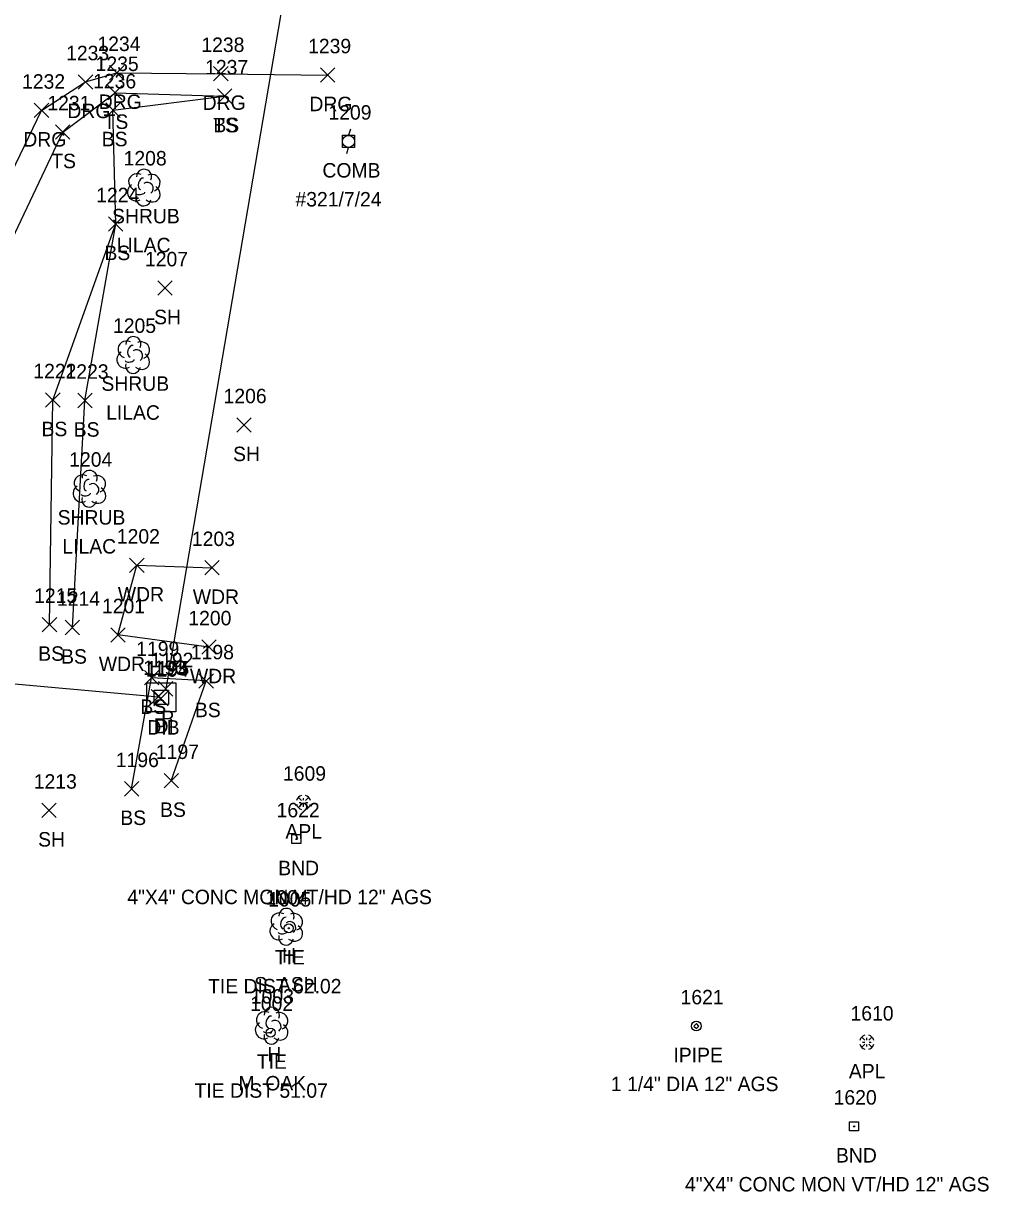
# Model space of a CAD drawing. Extents: x 1618262 to 1622220, y 273782 to 283685.
# Drawn here: x 1622086.2 to 1622219.5, y 282421 to 282582.4 of the extents above; entities that cross this region are included whole.
import ezdxf

# ---------------------------------------------------------------- set-up
doc = ezdxf.new("R2010")
doc.units = 0
for name, color, linetype in [('C_A', 7, 'Continuous'), ('C_C', 7, 'Continuous'), ('C_I', 7, 'Continuous'), ('CBP', 7, 'Continuous'), ('D_A', 7, 'Continuous'), ('D_I', 7, 'Continuous'), ('D_TIC', 7, 'Continuous'), ('DCP', 7, 'Continuous'), ('DS', 7, 'Continuous'), ('L_A', 7, 'Continuous'), ('L_C', 7, 'Continuous'), ('L_I', 7, 'Continuous'), ('L_TIC', 7, 'Continuous'), ('LAWA', 7, 'Continuous'), ('LELB', 7, 'Continuous'), ('LSH', 7, 'Continuous'), ('LTD', 7, 'Continuous'), ('M_A', 7, 'Continuous'), ('M_C', 7, 'Continuous'), ('M_I', 7, 'Continuous'), ('MHBP', 7, 'Continuous'), ('MMP', 7, 'Continuous'), ('MPIP', 7, 'Continuous'), ('R_A', 7, 'Continuous'), ('R_I', 7, 'Continuous'), ('R_TIC', 7, 'Continuous'), ('RDG', 7, 'Continuous'), ('U_A', 7, 'Continuous'), ('U_C', 7, 'Continuous'), ('U_I', 7, 'Continuous'), ('UP', 7, 'Continuous')]:
    doc.layers.add(name, color=color, linetype=linetype)

msp = doc.modelspace()

# ---------------------------------------------------------------- linework, layer by layer
at = {"layer": 'CBP'}
for centre, radius in [((1622122.83, 282457.39), 0.625), ((1622122.83, 282457.39), 0.0833), ((1622120.33, 282442.97), 0.625), ((1622120.33, 282442.97), 0.0833)]:
    msp.add_circle(centre, radius, dxfattribs=at)
at = {"layer": 'D_TIC'}
for points in [[(1622104.82, 282489.47), (1622106.82, 282491.47)], [(1622106.82, 282489.47), (1622104.82, 282491.47)], [(1622103.81, 282488.39), (1622105.81, 282490.39)], [(1622105.81, 282488.39), (1622103.81, 282490.39)], [(1622104.18, 282488.15), (1622106.18, 282490.15)], [(1622106.18, 282488.15), (1622104.18, 282490.15)]]:
    msp.add_lwpolyline(points, dxfattribs=at)
at = {"layer": 'DCP'}
for points in [[(1622123.83, 282596.22), (1622105.82, 282490.47)], [(1622012.08, 282497.76), (1622104.81, 282489.39)]]:
    msp.add_lwpolyline(points, dxfattribs=at)
at = {"layer": 'DS'}
for p, q in [((1622103.22, 282491.31), (1622107.22, 282491.31)), ((1622103.22, 282487.31), (1622103.22, 282491.31)), ((1622107.22, 282491.31), (1622107.22, 282487.31)), ((1622104.22, 282488.31), (1622104.22, 282490.31)), ((1622104.22, 282490.31), (1622106.22, 282490.31)), ((1622105.23, 282489.31), (1622105.23, 282489.31)), ((1622105.23, 282489.31), (1622105.23, 282489.31)), ((1622106.22, 282490.31), (1622106.22, 282488.31)), ((1622106.22, 282488.31), (1622104.22, 282488.31)), ((1622107.22, 282487.31), (1622103.22, 282487.31))]:
    msp.add_line(p, q, dxfattribs=at)
at = {"layer": 'L_TIC'}
for points in [[(1622097.83, 282571.85), (1622099.83, 282573.85)], [(1622099.83, 282571.85), (1622097.83, 282573.85)], [(1622112.97, 282571.38), (1622114.97, 282573.38)], [(1622114.97, 282571.38), (1622112.97, 282573.38)], [(1622112.97, 282571.38), (1622114.97, 282573.38)], [(1622114.97, 282571.38), (1622112.97, 282573.38)], [(1622097.53, 282569.45), (1622099.53, 282571.45)], [(1622099.53, 282569.45), (1622097.53, 282571.45)], [(1622090.59, 282566.42), (1622092.59, 282568.42)], [(1622092.59, 282566.42), (1622090.59, 282568.42)], [(1622097.92, 282553.72), (1622099.92, 282555.72)], [(1622099.92, 282553.72), (1622097.92, 282555.72)], [(1622097.92, 282553.72), (1622099.92, 282555.72)], [(1622099.92, 282553.72), (1622097.92, 282555.72)], [(1622104.73, 282544.86), (1622106.73, 282546.86)], [(1622106.73, 282544.86), (1622104.73, 282546.86)], [(1622089.22, 282529.39), (1622091.22, 282531.39)], [(1622091.22, 282529.39), (1622089.22, 282531.39)], [(1622093.67, 282529.32), (1622095.67, 282531.32)], [(1622095.67, 282529.32), (1622093.67, 282531.32)], [(1622115.64, 282525.94), (1622117.64, 282527.94)], [(1622117.64, 282525.94), (1622115.64, 282527.94)], [(1622100.84, 282506.55), (1622102.84, 282508.55)], [(1622102.84, 282506.55), (1622100.84, 282508.55)], [(1622111.21, 282506.21), (1622113.21, 282508.21)], [(1622113.21, 282506.21), (1622111.21, 282508.21)], [(1622088.76, 282498.35), (1622090.76, 282500.35)], [(1622090.76, 282498.35), (1622088.76, 282500.35)], [(1622091.93, 282497.95), (1622093.93, 282499.95)], [(1622093.93, 282497.95), (1622091.93, 282499.95)], [(1622098.22, 282496.92), (1622100.22, 282498.92)], [(1622100.22, 282496.92), (1622098.22, 282498.92)], [(1622110.8, 282495.25), (1622112.8, 282497.25)], [(1622112.8, 282495.25), (1622110.8, 282497.25)], [(1622102.88, 282491.01), (1622104.88, 282493.01)], [(1622104.88, 282491.01), (1622102.88, 282493.01)], [(1622102.88, 282491.01), (1622104.88, 282493.01)], [(1622104.88, 282491.01), (1622102.88, 282493.01)], [(1622110.42, 282490.56), (1622112.42, 282492.56)], [(1622112.42, 282490.56), (1622110.42, 282492.56)], [(1622105.6, 282476.78), (1622107.6, 282478.78)], [(1622107.6, 282476.78), (1622105.6, 282478.78)], [(1622100.11, 282475.66), (1622102.11, 282477.66)], [(1622102.11, 282475.66), (1622100.11, 282477.66)], [(1622088.71, 282472.68), (1622090.71, 282474.68)], [(1622090.71, 282472.68), (1622088.71, 282474.68)]]:
    msp.add_lwpolyline(points, dxfattribs=at)
at = {"layer": 'LAWA'}
msp.add_lwpolyline([(1622111.8, 282496.25), (1622099.22, 282497.92), (1622101.84, 282507.55), (1622112.21, 282507.21)], dxfattribs=at)
at = {"layer": 'LELB'}
for points in [[(1622078, 282475.26), (1622080.28, 282501.03), (1622081.04, 282531.01), (1622082.99, 282549.21), (1622091.59, 282567.42), (1622098.83, 282572.85), (1622113.97, 282572.38)], [(1622089.76, 282499.35), (1622090.22, 282530.39), (1622098.92, 282554.72), (1622098.53, 282570.45), (1622113.97, 282572.38)], [(1622092.93, 282498.95), (1622094.67, 282530.32), (1622098.92, 282554.72)], [(1622101.11, 282476.66), (1622103.88, 282492.01)], [(1622106.6, 282477.78), (1622111.42, 282491.56), (1622103.88, 282492.01)]]:
    msp.add_lwpolyline(points, dxfattribs=at)
at = {"layer": 'LSH'}
for p, q in [((1622102.78, 282559.8), (1622102.78, 282559.8)), ((1622102.78, 282559.8), (1622102.78, 282559.8)), ((1622101.31, 282536.66), (1622101.31, 282536.66)), ((1622101.31, 282536.66), (1622101.31, 282536.66)), ((1622095.26, 282518.17), (1622095.26, 282518.17)), ((1622095.26, 282518.17), (1622095.26, 282518.17))]:
    msp.add_line(p, q, dxfattribs=at)
for centre in [(1622102.83, 282561.23), (1622101.36, 282538.1), (1622095.31, 282519.61)]:
    msp.add_arc(centre, 1.05, 335.5272, 180.9563, dxfattribs=at)
for centre, major_axis, ratio, start_param, end_param in [((1622101.99, 282560.47), (1.21, -0.51), 0.895232, 1.570796, 4.712389), ((1622102.57, 282560.26), (-0.208, -0.792), 0.645439, 3.141593, 6.283185), ((1622103.28, 282559.63), (-0.5, 0.667), 0.989748, 3.141593, 6.283185), ((1622103.82, 282560.38), (-1.14, -0.48), 0.949671, 1.570796, 4.712389), ((1622101.7, 282559.09), (0.58, -1.04), 0.959034, 3.141593, 6.283185), ((1622102.32, 282559.05), (-0.625, -0.083), 0.423636, 0, 3.141593), ((1622103.78, 282558.97), (-1.09, 0.79), 0.841452, 1.570796, 4.712389), ((1622102.78, 282558.3), (0.26, 1.06), 0.942809, 1.570796, 4.712389), ((1622100.52, 282537.33), (1.21, -0.51), 0.895232, 1.570796, 4.712389), ((1622101.11, 282537.12), (-0.208, -0.792), 0.645439, 3.141593, 6.283185), ((1622102.36, 282537.25), (-1.14, -0.48), 0.949671, 1.570796, 4.712389), ((1622100.23, 282535.95), (0.58, -1.04), 0.959034, 3.141593, 6.283185), ((1622101.81, 282536.5), (-0.5, 0.667), 0.989748, 3.141593, 6.283185), ((1622102.32, 282535.83), (-1.09, 0.79), 0.841452, 1.570796, 4.712389), ((1622101.32, 282535.16), (0.26, 1.06), 0.942809, 1.570796, 4.712389), ((1622100.86, 282535.91), (-0.625, -0.083), 0.423636, 0, 3.141593), ((1622094.47, 282518.84), (1.21, -0.51), 0.895232, 1.570796, 4.712389), ((1622096.3, 282518.76), (-1.14, -0.48), 0.949671, 1.570796, 4.712389), ((1622094.18, 282517.46), (0.58, -1.04), 0.959034, 3.141593, 6.283185), ((1622095.05, 282518.63), (-0.208, -0.792), 0.645439, 3.141593, 6.283185), ((1622095.76, 282518.01), (-0.5, 0.667), 0.989748, 3.141593, 6.283185), ((1622095.26, 282516.67), (0.26, 1.06), 0.942809, 1.570796, 4.712389), ((1622094.8, 282517.42), (-0.625, -0.083), 0.423636, 0, 3.141593), ((1622096.26, 282517.34), (-1.09, 0.79), 0.841452, 1.570796, 4.712389)]:
    msp.add_ellipse(centre, major_axis=major_axis, ratio=ratio, start_param=start_param, end_param=end_param, dxfattribs=at)
at = {"layer": 'LTD'}
for p, q in [((1622122.47, 282457.65), (1622122.47, 282457.65)), ((1622122.47, 282457.65), (1622122.47, 282457.65)), ((1622120.44, 282443.98), (1622120.44, 282443.98)), ((1622120.44, 282443.98), (1622120.44, 282443.98))]:
    msp.add_line(p, q, dxfattribs=at)
for centre in [(1622122.51, 282459.09), (1622120.49, 282445.42)]:
    msp.add_arc(centre, 1.05, 335.5272, 180.9563, dxfattribs=at)
for centre, major_axis, ratio, start_param, end_param in [((1622121.67, 282458.32), (1.21, -0.51), 0.895232, 1.570796, 4.712389), ((1622122.26, 282458.11), (-0.208, -0.792), 0.645439, 3.141593, 6.283185), ((1622123.51, 282458.24), (-1.14, -0.48), 0.949671, 1.570796, 4.712389), ((1622121.38, 282456.95), (0.58, -1.04), 0.959034, 3.141593, 6.283185), ((1622122.01, 282456.9), (-0.625, -0.083), 0.423636, 0, 3.141593), ((1622122.97, 282457.49), (-0.5, 0.667), 0.989748, 3.141593, 6.283185), ((1622123.47, 282456.82), (-1.09, 0.79), 0.841452, 1.570796, 4.712389), ((1622122.47, 282456.15), (0.26, 1.06), 0.942809, 1.570796, 4.712389), ((1622119.65, 282444.65), (1.21, -0.51), 0.895232, 1.570796, 4.712389), ((1622121.48, 282444.57), (-1.14, -0.48), 0.949671, 1.570796, 4.712389), ((1622119.36, 282443.28), (0.58, -1.04), 0.959034, 3.141593, 6.283185), ((1622120.23, 282444.44), (-0.208, -0.792), 0.645439, 3.141593, 6.283185), ((1622120.94, 282443.82), (-0.5, 0.667), 0.989748, 3.141593, 6.283185), ((1622121.44, 282443.15), (-1.09, 0.79), 0.841452, 1.570796, 4.712389), ((1622120.44, 282442.48), (0.26, 1.06), 0.942809, 1.570796, 4.712389), ((1622119.98, 282443.23), (-0.625, -0.083), 0.423636, 0, 3.141593)]:
    msp.add_ellipse(centre, major_axis=major_axis, ratio=ratio, start_param=start_param, end_param=end_param, dxfattribs=at)
at = {"layer": 'MHBP'}
for points in [[(1622123.26, 282470.34), (1622124.51, 282470.34), (1622124.51, 282469.09), (1622123.26, 282469.09)], [(1622200.32, 282430.65), (1622201.57, 282430.65), (1622201.57, 282429.4), (1622200.32, 282429.4)]]:
    msp.add_lwpolyline(points, close=True, dxfattribs=at)
for centre in [(1622123.89, 282469.72), (1622200.95, 282430.02)]:
    msp.add_circle(centre, 0.0833, dxfattribs=at)
at = {"layer": 'MMP'}
for p, q in [((1622124.22, 282475.42), (1622124.58, 282475.06)), ((1622124.26, 282474.78), (1622124.56, 282474.78)), ((1622124.86, 282475.08), (1622124.86, 282475.38)), ((1622125.14, 282475.06), (1622125.5, 282475.42)), ((1622125.16, 282474.78), (1622125.46, 282474.78)), ((1622124.22, 282474.14), (1622124.58, 282474.5)), ((1622124.86, 282474.18), (1622124.86, 282474.48)), ((1622125.14, 282474.5), (1622125.5, 282474.14)), ((1622202.07, 282442.28), (1622202.43, 282441.92)), ((1622202.07, 282441), (1622202.43, 282441.36)), ((1622202.11, 282441.64), (1622202.41, 282441.64)), ((1622202.71, 282441.94), (1622202.71, 282442.24)), ((1622202.71, 282441.04), (1622202.71, 282441.34)), ((1622202.99, 282441.92), (1622203.35, 282442.28)), ((1622202.99, 282441.36), (1622203.35, 282441)), ((1622203.01, 282441.64), (1622203.31, 282441.64))]:
    msp.add_line(p, q, dxfattribs=at)
for centre, start, end in [((1622124.86, 282474.78), 105, 165), ((1622124.86, 282474.78), 15, 75), ((1622124.86, 282474.78), 195, 255), ((1622124.86, 282474.78), 285, 345), ((1622202.71, 282441.64), 105, 165), ((1622202.71, 282441.64), 15, 75), ((1622202.71, 282441.64), 195, 255), ((1622202.71, 282441.64), 285, 345)]:
    msp.add_arc(centre, 1, start, end, dxfattribs=at)
at = {"layer": 'MPIP'}
msp.add_lwpolyline([(1622179.48, 282443.88), (1622179.15, 282444.22), (1622178.81, 282443.88), (1622179.15, 282443.55)], close=True, dxfattribs=at)
msp.add_circle((1622179.15, 282443.88), 0.667, dxfattribs=at)
at = {"layer": 'R_TIC'}
for points in [[(1622098.08, 282574.61), (1622100.08, 282576.61)], [(1622100.08, 282574.61), (1622098.08, 282576.61)], [(1622112.44, 282574.48), (1622114.44, 282576.48)], [(1622114.44, 282574.48), (1622112.44, 282576.48)], [(1622093.75, 282573.34), (1622095.75, 282575.34)], [(1622095.75, 282573.34), (1622093.75, 282575.34)], [(1622127.2, 282574.3), (1622129.2, 282576.3)], [(1622129.2, 282574.3), (1622127.2, 282576.3)], [(1622087.66, 282569.41), (1622089.66, 282571.41)], [(1622089.66, 282569.41), (1622087.66, 282571.41)]]:
    msp.add_lwpolyline(points, dxfattribs=at)
at = {"layer": 'RDG'}
msp.add_lwpolyline([(1622082.72, 282558.14), (1622088.66, 282570.41), (1622094.75, 282574.34), (1622099.08, 282575.61), (1622113.44, 282575.48), (1622128.2, 282575.3)], dxfattribs=at)
at = {"layer": 'UP'}
for p, q in [((1622130.26, 282565.3), (1622130.26, 282566.97)), ((1622130.26, 282566.97), (1622131.93, 282566.97)), ((1622131.34, 282567.8), (1622131.09, 282566.97)), ((1622131.93, 282566.97), (1622131.93, 282565.3)), ((1622131.93, 282565.3), (1622130.26, 282565.3)), ((1622130.84, 282564.47), (1622131.09, 282565.3)), ((1622131.09, 282566.13), (1622131.09, 282566.13))]:
    msp.add_line(p, q, dxfattribs=at)
msp.add_circle((1622131.09, 282566.13), 0.833, dxfattribs=at)

# ---------------------------------------------------------------- texts
at = {"layer": 'C_A'}
for p in [(1622120.9, 282452.39), (1622118.41, 282437.97)]:
    msp.add_text('TIE', height=2, dxfattribs=at).set_placement(p)
at = {"layer": 'C_C'}
for s, p in [('TIE DIST 62.02', (1622111.68, 282448.39)), ('TIE DIST 51.07', (1622109.8, 282433.97))]:
    msp.add_text(s, height=2, dxfattribs=at).set_placement(p)
at = {"layer": 'C_I'}
for s, p in [('1005', (1622119.98, 282460.39)), ('1002', (1622117.48, 282445.97))]:
    msp.add_text(s, height=2, dxfattribs=at).set_placement(p)
at = {"layer": 'D_A'}
for s, p in [('DIB', (1622103.28, 282484.15)), ('P', (1622104.19, 282484.39)), ('DI', (1622104.28, 282484.31)), ('P', (1622105.2, 282485.47))]:
    msp.add_text(s, height=2, dxfattribs=at).set_placement(p)
at = {"layer": 'D_I'}
for s, p in [('1193', (1622102.69, 282492.39)), ('1194', (1622103.06, 282492.15)), ('1195', (1622103.1, 282492.31)), ('1192', (1622103.7, 282493.47))]:
    msp.add_text(s, height=2, dxfattribs=at).set_placement(p)
at = {"layer": 'L_A'}
for s, p in [('TS', (1622097.24, 282567.85)), ('TS', (1622112.38, 282567.38)), ('BS', (1622112.41, 282567.38)), ('BS', (1622096.98, 282565.45)), ('TS', (1622090, 282562.42)), ('SHRUB', (1622098.41, 282554.8)), ('BS', (1622097.36, 282549.72)), ('BS', (1622097.36, 282549.72)), ('SH', (1622104.22, 282540.86)), ('SHRUB', (1622096.94, 282531.66)), ('BS', (1622088.66, 282525.39)), ('BS', (1622093.11, 282525.32)), ('SH', (1622115.13, 282521.94)), ('SHRUB', (1622090.89, 282513.17)), ('WDR', (1622099.21, 282502.55)), ('WDR', (1622109.57, 282502.21)), ('BS', (1622088.21, 282494.35)), ('BS', (1622091.37, 282493.95)), ('WDR', (1622096.58, 282492.92)), ('WDR', (1622109.17, 282491.25)), ('BS', (1622102.32, 282487.01)), ('BS', (1622102.32, 282487.01)), ('BS', (1622109.86, 282486.56)), ('BS', (1622105.04, 282472.78)), ('BS', (1622099.55, 282471.66)), ('SH', (1622088.2, 282468.68)), ('H', (1622121.9, 282452.65)), ('H', (1622119.87, 282438.98))]:
    msp.add_text(s, height=2, dxfattribs=at).set_placement(p)
at = {"layer": 'L_C'}
for s, p in [('LILAC', (1622099.06, 282550.8)), ('LILAC', (1622097.59, 282527.66)), ('LILAC', (1622091.54, 282509.17)), ('S. ASH', (1622118.06, 282448.65)), ('M. OAK', (1622115.87, 282434.98))]:
    msp.add_text(s, height=2, dxfattribs=at).set_placement(p)
at = {"layer": 'L_I'}
for s, p in [('1235', (1622096.14, 282575.85)), ('1237', (1622111.27, 282575.38)), ('1237', (1622111.27, 282575.38)), ('1236', (1622095.79, 282573.45)), ('1231', (1622089.47, 282570.42)), ('1208', (1622100.01, 282562.8)), ('1224', (1622096.22, 282557.72)), ('1224', (1622096.22, 282557.72)), ('1207', (1622102.96, 282548.86)), ('1205', (1622098.54, 282539.66)), ('1222', (1622087.53, 282533.39)), ('1223', (1622091.98, 282533.32)), ('1206', (1622113.82, 282529.94)), ('1204', (1622092.49, 282521.17)), ('1202', (1622099.07, 282510.55)), ('1203', (1622109.44, 282510.21)), ('1215', (1622087.64, 282502.35)), ('1214', (1622090.8, 282501.95)), ('1201', (1622097.02, 282500.92)), ('1200', (1622108.95, 282499.25)), ('1199', (1622101.75, 282495.01)), ('1199', (1622101.75, 282495.01)), ('1198', (1622109.3, 282494.56)), ('1197', (1622104.47, 282480.78)), ('1196', (1622098.93, 282479.66)), ('1213', (1622087.59, 282476.68)), ('1004', (1622119.62, 282460.65)), ('1003', (1622117.59, 282446.98))]:
    msp.add_text(s, height=2, dxfattribs=at).set_placement(p)
at = {"layer": 'M_A'}
for s, p in [('APL', (1622122.37, 282469.78)), ('BND', (1622121.37, 282464.72)), ('IPIPE', (1622175.98, 282438.88)), ('APL', (1622200.22, 282436.64)), ('BND', (1622198.44, 282425.02))]:
    msp.add_text(s, height=2, dxfattribs=at).set_placement(p)
at = {"layer": 'M_C'}
for s, p in [('4"X4" CONC MON VT/HD 12" AGS', (1622100.52, 282460.72)), ('1 1/4" DIA 12" AGS', (1622167.34, 282434.88)), ('4"X4" CONC MON VT/HD 12" AGS', (1622177.58, 282421.02))]:
    msp.add_text(s, height=2, dxfattribs=at).set_placement(p)
at = {"layer": 'M_I'}
for s, p in [('1609', (1622122.03, 282477.78)), ('1622', (1622121.15, 282472.72)), ('1621', (1622176.97, 282446.88)), ('1610', (1622200.45, 282444.64)), ('1620', (1622198.12, 282433.02))]:
    msp.add_text(s, height=2, dxfattribs=at).set_placement(p)
at = {"layer": 'R_A'}
for p in [(1622096.57, 282570.61), (1622110.93, 282570.48), (1622125.68, 282570.3), (1622092.24, 282569.34), (1622086.15, 282565.41)]:
    msp.add_text('DRG', height=2, dxfattribs=at).set_placement(p)
at = {"layer": 'R_I'}
for s, p in [('1234', (1622096.39, 282578.61)), ('1238', (1622110.75, 282578.48)), ('1239', (1622125.5, 282578.3)), ('1233', (1622092.06, 282577.34)), ('1232', (1622085.97, 282573.41))]:
    msp.add_text(s, height=2, dxfattribs=at).set_placement(p)
at = {"layer": 'U_A'}
msp.add_text('COMB', height=2, dxfattribs=at).set_placement((1622127.48, 282561.13))
at = {"layer": 'U_C'}
msp.add_text('#321/7/24', height=2, dxfattribs=at).set_placement((1622123.75, 282557.13))
at = {"layer": 'U_I'}
msp.add_text('1209', height=2, dxfattribs=at).set_placement((1622128.31, 282569.13))

doc.saveas('drawing.dxf')
